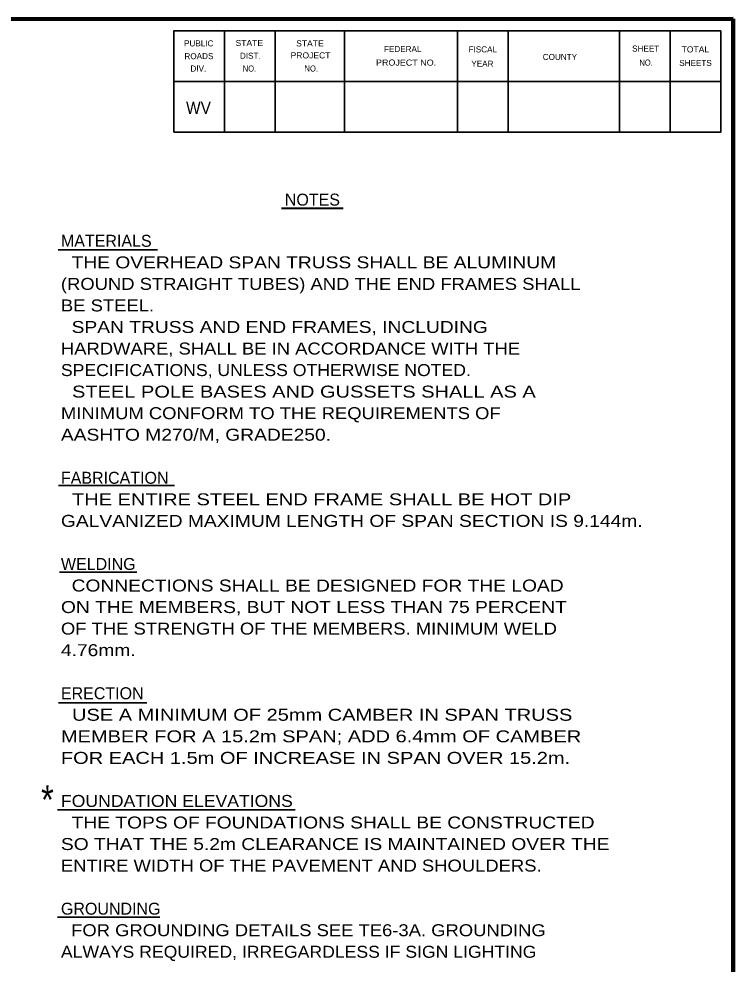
# Model space of a CAD drawing. Extents: x -29 to 827, y -14 to 530.
# Drawn here: x 641 to 820, y 286.3 to 523.3 of the extents above; entities that cross this region are included whole.
import ezdxf

# ---------------------------------------------------------------- set-up
doc = ezdxf.new("R2010")
doc.units = 0
doc.header["$LTSCALE"] = 0.97
doc.layers.add('1', color=7, linetype='Continuous', lineweight=53)
doc.layers.add('61', color=7, linetype='Continuous', lineweight=35)

msp = doc.modelspace()

# ---------------------------------------------------------------- linework, layer by layer
at = {"layer": '1', "lineweight": 158}
msp.add_line((820.0407, -2.8455), (820.0407, 523.2545), dxfattribs=at)
at = {"layer": '1', "lineweight": 13}
msp.add_line((820.0407, -2.8455), (820.0407, 523.2545), dxfattribs=at)
at = {"layer": '1', "lineweight": 40}
msp.add_line((706.8253, 475.7954), (722.3056, 475.7954), dxfattribs=at)
at = {"layer": '1', "lineweight": 35}
for p, q in [((650.8594, 465.3997), (675.7628, 465.3997)), ((650.9322, 406.272), (680.0267, 406.272)), ((651.2512, 384.567), (670.6417, 384.567)), ((650.9923, 351.8584), (673.1226, 351.8584)), ((650.7618, 325.0402), (710.3237, 325.0402)), ((650.7618, 298.0682), (676.3451, 298.0682))]:
    msp.add_line(p, q, dxfattribs=at)
at = {"layer": '1', "lineweight": 158}
msp.add_lwpolyline([(820.0407, 523.2545), (28.3407, 523.1545), (28.4407, -2.8455)], dxfattribs=at)
at = {"layer": '61'}
for p, q in [((692.5407, 520.2545), (692.5407, 494.8545)), ((705.2407, 520.2545), (705.2407, 494.8545)), ((722.6407, 520.2545), (722.6407, 494.8545)), ((750.9407, 520.2545), (750.9407, 494.8545)), ((763.6407, 520.2545), (763.6407, 494.8545)), ((791.5407, 520.2545), (791.5407, 494.8545)), ((804.2407, 520.2545), (804.2407, 494.8545)), ((816.9407, 507.5545), (679.8407, 507.5545))]:
    msp.add_line(p, q, dxfattribs=at)
for points in [[(816.9407, 520.2545), (679.8407, 520.2545), (679.8407, 494.8545)], [(816.9407, 520.2545), (816.9407, 494.8545), (679.8407, 494.8545)]]:
    msp.add_lwpolyline(points, dxfattribs=at)

# ---------------------------------------------------------------- texts
at = {"layer": '1'}
for s, height, width, p in [('WV', 3.048, 0.95, (682.9407, 499.4545)), ('  THE OVERHEAD SPAN TRUSS SHALL BE ALUMINUM', 3, 1.2, (651.5801, 460.732)), ('(ROUND STRAIGHT TUBES) AND THE END FRAMES SHALL', 3, 1.15, (651.5801, 455.332)), ('BE STEEL.', 3, 1.15, (651.5801, 449.932)), ('  SPAN TRUSS AND END FRAMES, INCLUDING', 3, 1.2, (651.5801, 444.532)), ('HARDWARE, SHALL BE IN ACCORDANCE WITH THE', 3, 1.15, (651.5801, 439.132)), ('SPECIFICATIONS, UNLESS OTHERWISE NOTED.', 3, 1.1, (651.5801, 433.732)), ('  STEEL POLE BASES AND GUSSETS SHALL AS A', 3, 1.25, (651.5801, 428.332)), ('MINIMUM CONFORM TO THE REQUIREMENTS OF', 3, 1.15, (651.5801, 422.932)), ('AASHTO M270/M, GRADE250.', 3, 1.2, (651.5801, 417.532)), ('  THE ENTIRE STEEL END FRAME SHALL BE HOT DIP', 3, 1.25, (651.5801, 401.332)), ('GALVANIZED MAXIMUM LENGTH OF SPAN SECTION IS 9.144m.', 3, 1.2, (651.5801, 395.932)), ('  CONNECTIONS SHALL BE DESIGNED FOR THE LOAD', 3, 1.2, (651.5801, 379.732)), ('ON THE MEMBERS, BUT NOT LESS THAN 75 PERCENT', 3, 1.2, (651.5801, 374.332)), ('OF THE STRENGTH OF THE MEMBERS. MINIMUM WELD', 3, 1.15, (651.5801, 368.932)), ('4.76mm.', 3, 1.2, (651.5801, 363.532)), ('  USE A MINIMUM OF 25mm CAMBER IN SPAN TRUSS', 3, 1.25, (651.5801, 347.332)), ('MEMBER FOR A 15.2m SPAN; ADD 6.4mm OF CAMBER', 3, 1.25, (651.5801, 341.932)), ('FOR EACH 1.5m OF INCREASE IN SPAN OVER 15.2m.', 3, 1.25, (651.5801, 336.532)), ('*', 7.2, 0.85, (646.6034, 323.9522)), ('FOUNDATION ELEVATIONS', 3, 1.1, (651.5801, 325.732)), ('  THE TOPS OF FOUNDATIONS SHALL BE CONSTRUCTED', 3, 1.2, (651.5801, 320.332)), ('SO THAT THE 5.2m CLEARANCE IS MAINTAINED OVER THE', 3, 1.2, (651.5801, 314.932)), ('ENTIRE WIDTH OF THE PAVEMENT AND SHOULDERS.', 3, 1.15, (651.5801, 309.532)), ('  FOR GROUNDING DETAILS SEE TE6-3A. GROUNDING', 3, 1.15, (651.5801, 293.332)), ('ALWAYS REQUIRED, IRREGARDLESS IF SIGN LIGHTING', 3, 1.1, (651.5801, 287.932))]:
    msp.add_text(s, height=height, dxfattribs=dict(at, width=width)).set_placement(p)
for s, p in [('NOTES', (707.696, 476.4558)), ('MATERIALS', (651.5801, 466.132)), ('FABRICATION', (651.5801, 406.732)), ('WELDING', (651.5801, 385.132)), ('ERECTION', (651.5801, 352.732)), ('GROUNDING', (651.5801, 298.732))]:
    msp.add_text(s, height=3, dxfattribs=at).set_placement(p)
at = {"layer": '61'}
for s, height, rotation, p in [('PUBLIC', 1.525, 0.033, (682.4407, 516.3545)), ('FEDERAL', 1.523, 0.007, (732.5407, 514.9545)), ('SHEET', 1.525, 0.059, (794.7407, 515.0545)), ('ROADS', 1.525, 0.124, (682.5407, 513.1545)), ('DIST.', 1.525, 0.056, (696.4407, 513.2545)), ('FISCAL', 1.525, 359.942, (753.7407, 514.8545)), ('COUNTY', 1.523, 0.069, (772.3407, 512.9545)), ('YEAR', 1.523, 0.105, (754.4407, 511.2545)), ('SHEETS', 1.523, 359.959, (806.5407, 511.4545)), ('DIV.', 1.525, 359.932, (684.0407, 510.0545))]:
    msp.add_text(s, height=height, rotation=rotation, dxfattribs=at).set_placement(p)
for s, rotation, width, p in [('STATE', 0.059, 1.05, (695.3407, 516.4545)), ('STATE', 0.059, 1.05, (710.5407, 516.3545)), ('PROJECT', 359.908, 1.05, (709.1407, 513.3545)), ('TOTAL', 359.926, 1.05, (807.1407, 514.8545)), ('PROJECT NO.', 359.922, 1.1, (730.5407, 511.5545)), ('NO.', 359.852, 0.9, (796.5407, 511.5545)), ('NO.', 359.852, 0.9, (697.1407, 510.0545)), ('NO.', 0.225, 0.9, (712.6407, 510.0545))]:
    msp.add_text(s, height=1.525, rotation=rotation, dxfattribs=dict(at, width=width)).set_placement(p)

doc.saveas('drawing.dxf')
